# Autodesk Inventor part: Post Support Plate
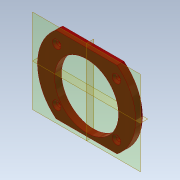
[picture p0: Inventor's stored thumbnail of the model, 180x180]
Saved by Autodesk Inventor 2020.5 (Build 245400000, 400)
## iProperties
LastFilename: FCG_Part.ipt
DataBaseUnit: MM
Created: 2023-05
Part Number: Post Support Plate
Material: Aluminum 6061
Document SubType Name: Modeling
Designer: A. Bennett
Mass: 98.8754 g
Surface Area: 146.088 cm^2
Volume: 36.6205 cm^3
Density: 2.7 g/cm^3
Appearance: Red
Author: A. Bennett
Revision Number: -
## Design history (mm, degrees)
sketch "Sketch10"
  geometry: L1 (35.795, -45)-(-35.795, -45); L2 (35.795, 45)-(-35.795, 45); L3 (-80.5, 0)-(80.5, 0) reference; L4 (35, -31)-(-35, -31); L5 (-35, -31)-(-35, 31); L6 (-35, 31)-(35, 31); L7 (35, 31)-(35, -31); L8 (35, -31)-(-35, 31); L9 (-35, -31)-(35, 31); L10 (0, -80.5)-(0, 80.5) reference; C1 r 37.5 at (0, -4); C2 r 2.75 at (35, -31); C3 r 2.75 at (35, 31); C4 r 2.75 at (-35, -31); C5 r 2.75 at (-35, 31); A1 r 57.5 centre (0, 0) between (35.795, -45) and (35.795, 45); A2 r 57.5 centre (0, 0) between (-35.795, -45) and (35.795, -45); A3 r 57.5 centre (0, 0) between (35.795, 45) and (-35.795, 45); A4 r 57.5 centre (0, 0) between (-35.795, 45) and (-35.795, -45); 1 further point
  constraints: 16 end point, 9 centre point, 9 point on circle, 5 coincident, 3 horizontal, 2 midpoint, 2 parallel, 1 perpendicular, 1 point on line
  dimensions: "d25" = 115 diameter of A1; "d26" = 45 distance between parallel lines of L1 L3; "d27" = 45 distance between parallel lines of L3 L2; "d28" = 75 diameter of C1; "d29" = 4 distance of point (0, 0) C1.centre; "d30" = 70 distance of L5.end L6.end; "d31" = 62 distance of L4.end L5.end; "d32" = 5.5 diameter of C2; "d33" = 5.5 diameter of C4 (= d32); "d34" = 5.5 diameter of C5 (= d32); "d35" = 5.5 diameter of C3 (= d32)
extrude "Profile" new body sketch "Sketch10" distance "d36" = 8; taper "d37" = 0 deg
chamfer "Chamfer1" distance "d38" = 2.25; stored, may be unused: second distance "d39" = 2, angle "d40" = 45 deg
sketch "Sketch11"
  geometry: C1 r 2.75 at (-35, 31) reference; C2 r 2.75 at (-35, -31) reference; C3 r 2.75 at (35, -31) reference; C4 r 2.75 at (35, 31) reference; 5 further points
  constraints: 4 coincident
hole "Corner Posts" sketch "Sketch11" at (-35, 31), (-35, -31), (35, -31), (35, 31) diameter "d41" = 8; stored, may be unused: countersink angle "d45" = 90 deg, drill point angle "d47" = 0 deg; dims "d42" = 6, "d43" = 9.8, "d44" = 2, "d46" = 3
sketch "Sketch12"
  geometry: L1 (0, 63)-(0, -63) reference; L2 (-35.795, -45)-(35.795, -45) reference; 2 further points
  constraints: 1 point on line
  dimensions: "d48" = 7 distance from line of L2 point (0, -38)
hole "Jacking Screw" sketch "Sketch12" at (0, -38) diameter "d49" = 6; stored, may be unused: countersink angle "d53" = 90 deg, drill point angle "d55" = 0 deg; dims "d50" = 6, "d51" = 9.8, "d52" = 2, "d54" = 2
body "Solid7"
other parameters: "OD" = 1 [user parameter], "OAL" = 1 [user parameter]
